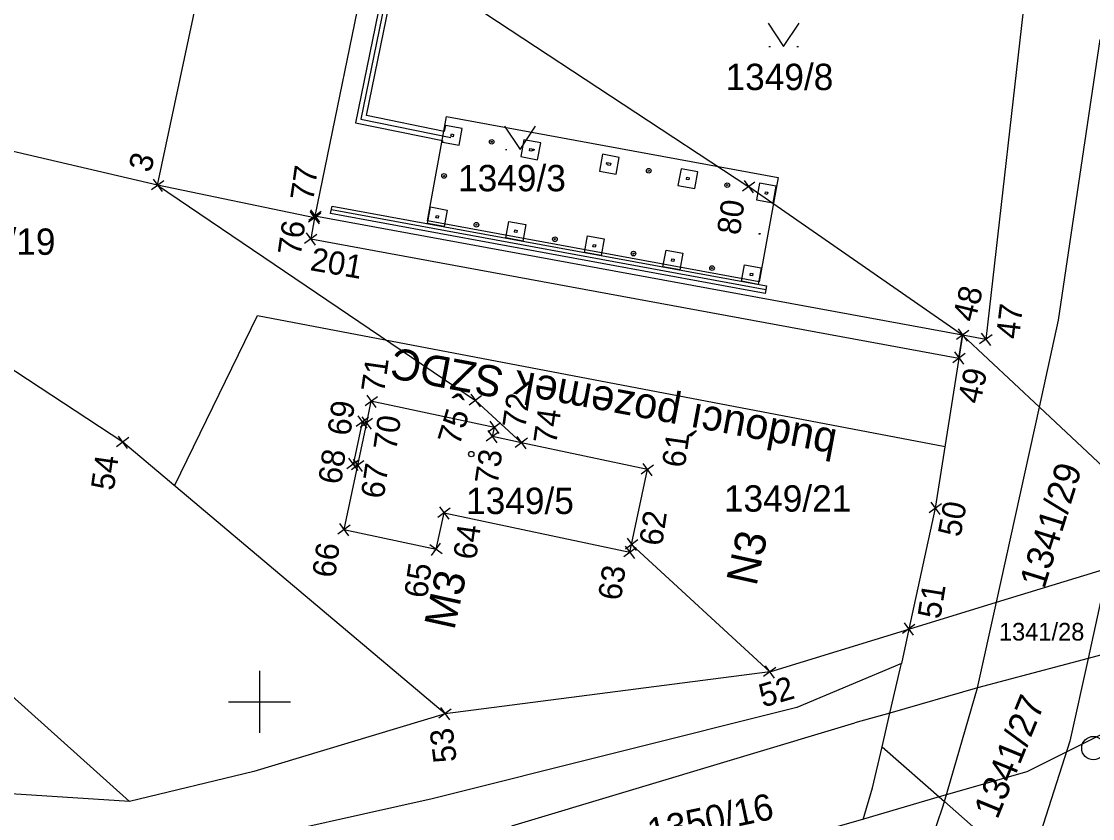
# Model space of a CAD drawing. Extents: x -735036 to -734743, y -1144813 to -1144181.
# Drawn here: x -734915.4 to -734846.3, y -1144707.5 to -1144656.1 of the extents above; entities that cross this region are included whole.
import ezdxf

# ---------------------------------------------------------------- set-up
doc = ezdxf.new("R2010")
doc.units = 0
for name, color, linetype in [('A3_ODVODŇOVACÍ ŽLAB', 7, 'Continuous'), ('A3_SIT_OBJEKT_N', 7, 'Continuous'), ('A3_SIT_OBJEKTY_N01', 7, 'Continuous'), ('BPEJ', 7, 'Continuous'), ('CKEL_VEDENI_NN_PODZ_N', 7, 'Continuous'), ('Groma (60)', 7, 'Continuous'), ('hranice pl. určené SŽDC', 7, 'Continuous'), ('Katastr_HRANICE DRÁHY', 7, 'Continuous'), ('Katastr_Hranice parcel', 7, 'Continuous'), ('Katastr_Parcelní čísla', 7, 'Continuous'), ('Katastr_Slučkované čáry', 7, 'Continuous'), ('Katastr_Značky kultur', 7, 'Continuous'), ('Vrstva 7', 7, 'Continuous'), ('ZÁBORY_dočasné', 7, 'Continuous'), ('čtvercová síť', 7, 'Continuous')]:
    doc.layers.add(name, color=color, linetype=linetype)

# ---------------------------------------------------------------- blocks, each defined once
blk = doc.blocks.new('C691')
at = {"layer": 'Vrstva 7'}
for p, q in [((0, 0.5), (0, -0.5)), ((-0.5, 0), (0.5, 0))]:
    blk.add_line(p, q, dxfattribs=at)
blk = doc.blocks.new('POINT_DISPLAY')
for p, q in [((-0.35, -0.35), (0.35, 0.35)), ((-0.35, 0.35), (0.35, -0.35))]:
    blk.add_line(p, q)

msp = doc.modelspace()

# ---------------------------------------------------------------- linework, layer by layer
at = {"layer": 'A3_ODVODŇOVACÍ ŽLAB'}
msp.add_line((-734867.335, -1144673.401), (-734895.365, -1144668.247), dxfattribs=at)
at = {"layer": 'A3_SIT_OBJEKT_N'}
for p, q in [((-734895.423, -1144668.491), (-734895.307, -1144668.004)), ((-734895.307, -1144668.004), (-734867.29, -1144673.155)), ((-734867.38, -1144673.647), (-734895.423, -1144668.491)), ((-734867.29, -1144673.155), (-734867.38, -1144673.647))]:
    msp.add_line(p, q, dxfattribs=at)
at = {"layer": 'A3_SIT_OBJEKTY_N01'}
for p, q in [((-734887.652, -1144663.499), (-734887.625, -1144663.352)), ((-734887.625, -1144663.352), (-734887.477, -1144663.379)), ((-734887.477, -1144663.379), (-734887.504, -1144663.527)), ((-734887.504, -1144663.527), (-734887.652, -1144663.499)), ((-734885.059, -1144663.885), (-734885.048, -1144663.826)), ((-734885, -1144663.896), (-734885.059, -1144663.885)), ((-734885.048, -1144663.826), (-734884.989, -1144663.837)), ((-734884.989, -1144663.837), (-734885, -1144663.896)), ((-734882.587, -1144664.431), (-734882.56, -1144664.283)), ((-734882.439, -1144664.458), (-734882.587, -1144664.431)), ((-734882.56, -1144664.283), (-734882.314, -1144664.328)), ((-734882.43, -1144664.409), (-734882.439, -1144664.458)), ((-734882.332, -1144664.427), (-734882.43, -1144664.409)), ((-734882.314, -1144664.328), (-734882.332, -1144664.427)), ((-734877.611, -1144665.295), (-734877.593, -1144665.196)), ((-734877.513, -1144665.313), (-734877.611, -1144665.295)), ((-734877.593, -1144665.196), (-734877.347, -1144665.242)), ((-734877.522, -1144665.362), (-734877.513, -1144665.313)), ((-734877.374, -1144665.389), (-734877.522, -1144665.362)), ((-734877.347, -1144665.242), (-734877.374, -1144665.389)), ((-734888.128, -1144666.086), (-734888.117, -1144666.027)), ((-734888.069, -1144666.097), (-734888.128, -1144666.086)), ((-734888.117, -1144666.027), (-734888.058, -1144666.038)), ((-734888.058, -1144666.038), (-734888.069, -1144666.097)), ((-734874.929, -1144665.747), (-734874.918, -1144665.688)), ((-734874.87, -1144665.758), (-734874.929, -1144665.747)), ((-734874.918, -1144665.688), (-734874.859, -1144665.699)), ((-734874.859, -1144665.699), (-734874.87, -1144665.758)), ((-734872.457, -1144666.293), (-734872.43, -1144666.146)), ((-734872.43, -1144666.146), (-734872.282, -1144666.173)), ((-734872.282, -1144666.173), (-734872.309, -1144666.32)), ((-734872.309, -1144666.32), (-734872.457, -1144666.293)), ((-734869.864, -1144666.679), (-734869.853, -1144666.62)), ((-734869.805, -1144666.689), (-734869.864, -1144666.679)), ((-734869.853, -1144666.62), (-734869.794, -1144666.63)), ((-734869.794, -1144666.63), (-734869.805, -1144666.689)), ((-734867.392, -1144667.225), (-734867.364, -1144667.077)), ((-734867.244, -1144667.252), (-734867.392, -1144667.225)), ((-734867.364, -1144667.077), (-734867.217, -1144667.104)), ((-734867.217, -1144667.104), (-734867.244, -1144667.252)), ((-734888.619, -1144668.761), (-734888.592, -1144668.614)), ((-734888.472, -1144668.788), (-734888.619, -1144668.761)), ((-734888.592, -1144668.614), (-734888.445, -1144668.641)), ((-734888.445, -1144668.641), (-734888.472, -1144668.788)), ((-734886.043, -1144669.235), (-734886.032, -1144669.176)), ((-734885.984, -1144669.246), (-734886.043, -1144669.235)), ((-734886.032, -1144669.176), (-734885.973, -1144669.187)), ((-734885.973, -1144669.187), (-734885.984, -1144669.246)), ((-734883.554, -1144669.693), (-734883.527, -1144669.545)), ((-734883.527, -1144669.545), (-734883.38, -1144669.572)), ((-734883.38, -1144669.572), (-734883.407, -1144669.72)), ((-734883.407, -1144669.72), (-734883.554, -1144669.693)), ((-734880.978, -1144670.166), (-734880.967, -1144670.107)), ((-734880.918, -1144670.177), (-734880.978, -1144670.166)), ((-734880.967, -1144670.107), (-734880.908, -1144670.118)), ((-734880.908, -1144670.118), (-734880.918, -1144670.177)), ((-734867.779, -1144669.828), (-734867.768, -1144669.769)), ((-734867.72, -1144669.838), (-734867.779, -1144669.828)), ((-734867.768, -1144669.769), (-734867.709, -1144669.779)), ((-734867.709, -1144669.779), (-734867.72, -1144669.838)), ((-734878.489, -1144670.624), (-734878.462, -1144670.476)), ((-734878.342, -1144670.651), (-734878.489, -1144670.624)), ((-734878.462, -1144670.476), (-734878.315, -1144670.503)), ((-734878.315, -1144670.503), (-734878.342, -1144670.651)), ((-734875.912, -1144671.098), (-734875.902, -1144671.039)), ((-734875.902, -1144671.039), (-734875.843, -1144671.049)), ((-734875.853, -1144671.108), (-734875.912, -1144671.098)), ((-734875.843, -1144671.049), (-734875.853, -1144671.108)), ((-734873.424, -1144671.555), (-734873.397, -1144671.408)), ((-734873.277, -1144671.582), (-734873.424, -1144671.555)), ((-734873.397, -1144671.408), (-734873.249, -1144671.435)), ((-734873.249, -1144671.435), (-734873.277, -1144671.582)), ((-734870.847, -1144672.029), (-734870.836, -1144671.97)), ((-734870.788, -1144672.04), (-734870.847, -1144672.029)), ((-734870.836, -1144671.97), (-734870.777, -1144671.981)), ((-734870.777, -1144671.981), (-734870.788, -1144672.04)), ((-734868.359, -1144672.486), (-734868.332, -1144672.339)), ((-734868.332, -1144672.339), (-734868.184, -1144672.366)), ((-734868.184, -1144672.366), (-734868.211, -1144672.514)), ((-734868.211, -1144672.514), (-734868.359, -1144672.486))]:
    msp.add_line(p, q, dxfattribs=at)
for points in [[(-734888.186, -1144663.779), (-734888.205, -1144663.881), (-734887.123, -1144664.08), (-734886.924, -1144662.998), (-734888.006, -1144662.799), (-734888.078, -1144663.189), (-734893.105, -1144662.162), (-734882.299, -1144609.423), (-734883.984, -1144609.076), (-734885.528, -1144610.071), (-734884.699, -1144610.25), (-734883.865, -1144609.713), (-734883.007, -1144609.89), (-734893.813, -1144662.63)], [(-734889.165, -1144668.966), (-734887.927, -1144662.229), (-734866.535, -1144666.162), (-734867.774, -1144672.899)], [(-734882.941, -1144663.73), (-734883.14, -1144664.812), (-734882.058, -1144665.011), (-734881.859, -1144663.929)], [(-734877.876, -1144664.661), (-734878.075, -1144665.743), (-734876.993, -1144665.942), (-734876.794, -1144664.86)], [(-734872.811, -1144665.593), (-734873.01, -1144666.675), (-734871.928, -1144666.874), (-734871.729, -1144665.792)], [(-734867.746, -1144666.524), (-734867.945, -1144667.606), (-734866.863, -1144667.805), (-734866.664, -1144666.723)], [(-734889.17, -1144669.132), (-734888.974, -1144668.061), (-734887.892, -1144668.26), (-734888.089, -1144669.331)], [(-734884.105, -1144670.063), (-734883.908, -1144668.992), (-734882.827, -1144669.191), (-734883.024, -1144670.262)], [(-734879.04, -1144670.994), (-734878.843, -1144669.923), (-734877.762, -1144670.122), (-734877.958, -1144671.193)], [(-734873.975, -1144671.926), (-734873.778, -1144670.855), (-734872.696, -1144671.053), (-734872.893, -1144672.125)], [(-734868.91, -1144672.857), (-734868.713, -1144671.786), (-734867.631, -1144671.985), (-734867.828, -1144673.056)]]:
    msp.add_lwpolyline(points, close=True, dxfattribs=at)
for centre in [(-734885.024, -1144663.861), (-734888.093, -1144666.062), (-734874.894, -1144665.723), (-734869.829, -1144666.655), (-734886.008, -1144669.211), (-734880.943, -1144670.142), (-734875.877, -1144671.074), (-734870.812, -1144672.005)]:
    msp.add_circle(centre, 0.15, dxfattribs=at)
at = {"layer": 'BPEJ'}
msp.add_lwpolyline([(-734875.407, -1144811.459), (-734872.9, -1144805.78), (-734867.89, -1144794.43), (-734854.34, -1144763.72), (-734850.2, -1144754.32), (-734842.33, -1144736.48), (-734836.55, -1144723.38), (-734836.47, -1144723.21), (-734828.55, -1144705.26), (-734828.47, -1144705.07), (-734837.14, -1144702.69), (-734834.01, -1144696), (-734841.2, -1144699.67), (-734841.55, -1144701.48), (-734843.42, -1144700.96), (-734850.5, -1144704.5), (-734856.16, -1144706.13), (-734861.05, -1144707.56), (-734878.02, -1144712.44), (-734888.06, -1144715.34), (-734896.33, -1144716.95), (-734914.06, -1144720.39), (-734915.89, -1144720.74)], dxfattribs=at)
at = {"layer": 'CKEL_VEDENI_NN_PODZ_N'}
msp.add_lwpolyline([(-734885.114, -1144610.161), (-734883.925, -1144609.395), (-734882.653, -1144609.657), (-734893.459, -1144662.396), (-734887.667, -1144663.579)], dxfattribs=at)
at = {"layer": 'hranice pl. určené SŽDC'}
for p, q in [((-734905.48, -1144686.06), (-734900.12, -1144675.07)), ((-734900.12, -1144675.07), (-734855.78, -1144683.52))]:
    msp.add_line(p, q, dxfattribs=at)
at = {"layer": 'Katastr_HRANICE DRÁHY'}
for p, q in [((-734906.57, -1144666.66), (-734899.28, -1144632.27)), ((-734906.57, -1144666.66), (-734930.18, -1144661.14)), ((-734867.09, -1144698.06), (-734888.03, -1144700.76))]:
    msp.add_line(p, q, dxfattribs=at)
for points in [[(-734850.42, -1144652.54), (-734853.15, -1144676.61)], [(-734908.82, -1144683.24), (-734932.55, -1144667.65)], [(-734854.65, -1144676.33), (-734856.41, -1144687.5)], [(-734853.15, -1144676.61), (-734854.65, -1144676.33)], [(-734888.03, -1144700.76), (-734908.82, -1144683.24)], [(-734856.41, -1144687.5), (-734858.12, -1144695.3)], [(-734867.09, -1144698.06), (-734858.12, -1144695.3)]]:
    msp.add_lwpolyline(points, dxfattribs=at)
at = {"layer": 'Katastr_Hranice parcel'}
for points in [[(-734892.76, -1144650.74), (-734896.42, -1144668.65)], [(-734892.76, -1144650.74), (-734868.44, -1144666.76)], [(-734896.45, -1144668.76), (-734906.57, -1144666.66)], [(-734906.57, -1144666.66), (-734886.07, -1144680.55)], [(-734854.65, -1144676.33), (-734868.44, -1144666.76)], [(-734896.42, -1144668.65), (-734896.45, -1144668.76)], [(-734854.65, -1144676.33), (-734896.42, -1144668.65)], [(-734849.69, -1144680.98), (-734854.65, -1144676.33)], [(-734892.81, -1144680.6), (-734893.1, -1144682)], [(-734884.85, -1144682.29), (-734892.81, -1144680.6)], [(-734886.07, -1144680.55), (-734883.11, -1144683.28)], [(-734844.19, -1144686.14), (-734849.69, -1144680.98)], [(-734908.39, -1144706.42), (-734935.61, -1144682)], [(-734893.37, -1144681.94), (-734893.96, -1144684.67)], [(-734893.1, -1144682), (-734893.37, -1144681.94)], [(-734884.98, -1144682.88), (-734884.85, -1144682.29)], [(-734883.11, -1144683.28), (-734884.98, -1144682.88)], [(-734874.98, -1144685.01), (-734883.11, -1144683.28)], [(-734893.67, -1144684.73), (-734894.55, -1144688.88)], [(-734893.96, -1144684.67), (-734893.67, -1144684.73)], [(-734876, -1144689.84), (-734874.98, -1144685.01)], [(-734888.61, -1144690.15), (-734888.09, -1144687.8)], [(-734888.09, -1144687.8), (-734876.11, -1144690.34)], [(-734894.55, -1144688.88), (-734888.61, -1144690.15)], [(-734876.11, -1144690.34), (-734876, -1144689.84)], [(-734876, -1144689.84), (-734867.09, -1144698.06)], [(-734852.46, -1144693.56), (-734845.28, -1144691.36)], [(-734858.12, -1144695.3), (-734852.46, -1144693.56)], [(-734858.12, -1144695.3), (-734858.6, -1144697.51)], [(-734840.41, -1144695.55), (-734846.56, -1144697.19)], [(-734846.56, -1144697.19), (-734853.68, -1144699.09)], [(-734858.6, -1144697.51), (-734865.34, -1144700.35)], [(-734859.34, -1144700.73), (-734858.65, -1144697.78)], [(-734858.65, -1144697.78), (-734858.6, -1144697.51)], [(-734853.68, -1144699.09), (-734859.34, -1144700.73)], [(-734865.34, -1144700.35), (-734888.87, -1144706.25)], [(-734859.34, -1144700.73), (-734861.61, -1144701.35)], [(-734859.84, -1144702.9), (-734859.34, -1144700.73)], [(-734888.03, -1144700.76), (-734900.37, -1144704.49)], [(-734883.72, -1144707.99), (-734861.61, -1144701.35)], [(-734860.46, -1144705.55), (-734859.84, -1144702.9)], [(-734859.84, -1144702.9), (-734855.82, -1144706.43)], [(-734900.37, -1144704.49), (-734908.39, -1144706.42)], [(-734908.39, -1144706.42), (-734927.72, -1144705.17)], [(-734861.06, -1144707.58), (-734860.46, -1144705.55)], [(-734888.87, -1144706.25), (-734902.35, -1144709.26)], [(-734855.82, -1144706.43), (-734850.48, -1144711.13)]]:
    msp.add_lwpolyline(points, dxfattribs=at)
at = {"layer": 'Katastr_Slučkované čáry'}
for points in [[(-734848.46, -1144675.36), (-734845.78, -1144657.26)], [(-734849.69, -1144680.98), (-734848.46, -1144675.36)], [(-734852.46, -1144693.56), (-734849.69, -1144680.98)], [(-734893.1, -1144682), (-734893.67, -1144684.73)], [(-734845.28, -1144691.36), (-734846.56, -1144697.19)], [(-734853.68, -1144699.09), (-734852.46, -1144693.56)], [(-734846.56, -1144697.19), (-734847.73, -1144702.54)], [(-734855.82, -1144706.43), (-734853.68, -1144699.09)], [(-734847.73, -1144702.54), (-734850.48, -1144711.13)], [(-734859.82, -1144718.19), (-734855.94, -1144706.83)], [(-734855.94, -1144706.83), (-734855.82, -1144706.43)]]:
    msp.add_lwpolyline(points, dxfattribs=at)
at = {"layer": 'Katastr_Značky kultur'}
for p, q in [((-734867.14, -1144657.71), (-734867.04, -1144657.71)), ((-734865.34, -1144657.71), (-734865.24, -1144657.71)), ((-734884.14, -1144664.35), (-734884.04, -1144664.35)), ((-734882.34, -1144664.35), (-734882.24, -1144664.35))]:
    msp.add_line(p, q, dxfattribs=at)
for points in [[(-734867.19, -1144656.21), (-734866.19, -1144657.71), (-734865.19, -1144656.21)], [(-734884.19, -1144662.85), (-734883.19, -1144664.35), (-734882.19, -1144662.85)]]:
    msp.add_lwpolyline(points, dxfattribs=at)
for centre, radius in [((-734886.34, -1144684.01), 0.175), ((-734846.21, -1144702.98), 0.756)]:
    msp.add_circle(centre, radius, dxfattribs=at)
at = {"layer": 'ZÁBORY_dočasné'}
for p, q in [((-734896.45, -1144668.76), (-734896.692, -1144670.129)), ((-734896.42, -1144668.65), (-734896.45, -1144668.76)), ((-734854.65, -1144676.33), (-734896.42, -1144668.65)), ((-734896.692, -1144670.129), (-734854.884, -1144677.816)), ((-734854.884, -1144677.816), (-734854.65, -1144676.33))]:
    msp.add_line(p, q, dxfattribs=at)

# ---------------------------------------------------------------- block references
at = {"layer": 'Groma (60)'}
for p, rotation in [((-734906.57, -1144666.66), -98.65482414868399), ((-734868.44, -1144666.76), -98.65482414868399), ((-734896.42, -1144668.65), -98.65482414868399), ((-734896.45, -1144668.76), -98.65482414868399), ((-734896.692, -1144670.129), -98.65482414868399), ((-734854.65, -1144676.33), -98.65482414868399), ((-734853.15, -1144676.61), -98.65482414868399), ((-734854.884, -1144677.816), -98.65482414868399), ((-734892.793, -1144680.604), -98.65482414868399), ((-734886.07, -1144680.55), -98.65482414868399), ((-734893.37, -1144681.94), -98.65482414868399), ((-734893.1, -1144682), -98.65482414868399), ((-734884.85, -1144682.29), -98.65482414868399), ((-734884.98, -1144682.88), -98.65482414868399), ((-734908.82, -1144683.24), -98.65482414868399), ((-734883.11, -1144683.28), -98.65482414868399), ((-734893.96, -1144684.67), -98.65482414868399), ((-734893.67, -1144684.73), -98.65482414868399), ((-734874.98, -1144685.01), -98.65482414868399), ((-734888.09, -1144687.8), -98.65482414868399), ((-734856.41, -1144687.5), -98.65482414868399), ((-734894.55, -1144688.88), -98.65482414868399), ((-734876, -1144689.84), -98.65482414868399), ((-734888.61, -1144690.15), 98.65482414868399), ((-734876.11, -1144690.34), -98.65482414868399), ((-734858.12, -1144695.3), -98.65482414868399), ((-734867.09, -1144698.06), -98.65482414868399), ((-734888.03, -1144700.76), -98.65482414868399)]:
    msp.add_blockref('POINT_DISPLAY', p, dxfattribs=dict(at, rotation=rotation))
at = {"layer": 'čtvercová síť', "xscale": 4, "yscale": 4}
msp.add_blockref('C691', (-734900, -1144700), dxfattribs=at)

# ---------------------------------------------------------------- texts
at = {"layer": 'Groma (60)'}
for s, rotation, p in [('3', 73.52326, (-734907.046, -1144665.908)), ('77', 81.78352, (-734896.54, -1144667.725)), ('80', 81.78352, (-734869.02, -1144669.921)), ('76', 81.78352, (-734897.347, -1144671.258)), ('201', 350.16241, (-734896.793, -1144672.135)), ('48', 76.15527, (-734853.857, -1144675.548)), ('47', 83.08955, (-734851.015, -1144676.632)), ('71', 81.78352, (-734891.971, -1144680.095)), ('49', 77.43307, (-734853.524, -1144680.83)), ('69', 81.78352, (-734894.15, -1144682.883)), ('72', 81.78352, (-734882.861, -1144682.408)), ('75', 72.96011, (-734887.107, -1144683.515)), ('74', 81.78352, (-734880.863, -1144683.417)), ('70', 81.78352, (-734891.181, -1144683.832)), ('61', 81.78352, (-734872.572, -1144684.94)), ('68', 81.78352, (-734894.743, -1144686.013)), ('73', 81.78352, (-734884.64, -1144686.023)), ('54', 81.78352, (-734909.401, -1144686.406)), ('67', 81.78352, (-734891.993, -1144686.941)), ('50', 79.36381, (-734854.788, -1144689.414)), ('62', 81.78352, (-734874.033, -1144689.986)), ('64', 81.78352, (-734886.035, -1144690.879)), ('66', 81.78352, (-734895.131, -1144692.046)), ('65', 81.78352, (-734889.2, -1144693.358)), ('63', 81.78352, (-734876.691, -1144693.506)), ('51', 80.83143, (-734856.088, -1144694.702)), ('52', 16.18947, (-734867.529, -1144700.364)), ('53', 97.26309, (-734887.267, -1144703.823))]:
    msp.add_text(s, height=1.5, rotation=rotation, dxfattribs=at).set_placement(p)
at = {"layer": 'hranice pl. určené SŽDC'}
for s, rotation, p in [('budoucí pozemek SŽDC', 169.4202, (-734862.661, -1144682.462)), ('N3', 77.55748, (-734867.954, -1144692.575)), ('M3', 77.55748, (-734887.44, -1144695.416))]:
    msp.add_text(s, height=2, rotation=rotation, dxfattribs=at).set_placement(p)
at = {"layer": 'Katastr_Parcelní čísla'}
for s, height, p in [('1349/8', 1.7, (-734869.94, -1144660.52)), ('1349/3', 1.7, (-734887.19, -1144667.05)), ('1349/19', 1.7, (-734921.376, -1144671.15)), ('1349/5', 1.7, (-734886.673, -1144687.875)), ('1349/21', 1.7, (-734870.043, -1144687.72)), ('1341/28', 1.14, (-734852.306, -1144696.04))]:
    msp.add_text(s, height=height, dxfattribs=at).set_placement(p)
for s, rotation, p in [('1341/29', 72.64242, (-734849.383, -1144692.759)), ('1341/27', 67.77648, (-734852.409, -1144707.632)), ('1350/16', 11.99088, (-734874.767, -1144709.232))]:
    msp.add_text(s, height=1.7, rotation=rotation, dxfattribs=at).set_placement(p)

doc.saveas('drawing.dxf')
